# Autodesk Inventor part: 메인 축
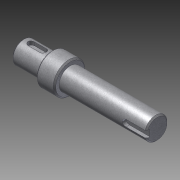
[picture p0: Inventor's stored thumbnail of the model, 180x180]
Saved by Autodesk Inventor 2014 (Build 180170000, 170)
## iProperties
Created: 2016-04
Part Number: 메인 축
Document SubType Name: Modeling
Designer: mdu
Density: 7.86 g/cm^3
Mass: 204.872 g
Surface Area: 67.8497 cm^2
Volume: 26.0651 cm^3
Material: 강철, 연강
Appearance: 반광택
Author: mdu
Revision Number: 1
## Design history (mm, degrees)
sketch "스케치1"
  geometry: L1 (10.497, -57.5)-(112.497, -57.5); L2 (10.497, -66)-(32.497, -66); L3 (32.497, -69.5)-(46.5, -69.5); L4 (46.5, -66)-(112.497, -66); L5 (112.497, -66)-(112.497, -57.5); L6 (10.497, -66)-(10.497, -57.5); L7 (46.5, -69.749)-(46.5, -45.251) reference; L8 (46.5, -69.5)-(46.5, -66); L9 (32.497, -69.5)-(32.497, -66); L10 (32.497, -35)-(32.497, -80) reference; 3 further points
  constraints: 16 end point, 3 point on line, 2 parallel, 2 perpendicular, 1 collinear, 1 horizontal, 1 midpoint
  dimensions: "d0" = 17 diameter of L4 L1; "d1" = 24 diameter of L3 L1; "d2" = 22 distance of L2.start L2.end; "d3" = 65.99692 distance of L4.start L4.end (derived); "d5" = 17 diameter of L2 L1; "d19" = 80 distance between parallel lines of L5 L9
revolve "회전1" sketch "스케치1" stored, may be unused: angle "d4" = 90 deg
feature "면 이동1"
chamfer "모따기1" distance "d6" = 0.5; stored, may be unused: second distance "d7" = 2, angle "d8" = 45 deg
node "작업 평면1"
sketch "스케치2"
  geometry: L1 (-11, -8)-(-11, 8) reference; L2 (-4.5, 2.5)-(4.5, 2.5); L3 (4.5, -2.5)-(-4.5, -2.5); A1 r 2.5 centre (4.5, 0) between (4.5, -2.5) and (4.5, 2.5); A2 r 2.5 centre (-4.5, 0) between (-4.5, 2.5) and (-4.5, -2.5); 2 further points
  constraints: 4 end point, 4 point on circle, 4 tangent, 2 centre point, 1 horizontal alignment, 1 midpoint, 1 parallel, 1 perpendicular
  dimensions: "d9" = 5 distance between parallel lines of L3 L2; "d10" = 14 dimension on A1 A2; "d11" = 4 distance edge to line of A2 L1
extrude "돌출1" cut sketch "스케치2" distance "d12" = 3; taper "d13" = 0 deg
node "작업 평면2"
sketch "스케치3"
  geometry: L1 (32.998, 8)-(32.998, -8) reference; L2 (32.998, 2.5)-(17.498, 2.5); L3 (17.498, -2.5)-(32.998, -2.5); A1 r 2.5 centre (17.498, 0) between (17.498, 2.5) and (17.498, -2.5); 2 further points
  constraints: 4 end point, 2 perpendicular, 2 point on circle, 2 point on line, 2 tangent, 1 centre point, 1 horizontal alignment, 1 midpoint
  dimensions: "d14" = 5 distance between parallel lines of L3 L2; "d15" = 18 dimension on A1 L1
extrude "돌출2" cut sketch "스케치3" distance "d16" = 3; taper "d17" = 0 deg
node "솔리드1"
node "참조4"
node "참조5"
